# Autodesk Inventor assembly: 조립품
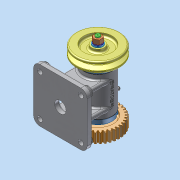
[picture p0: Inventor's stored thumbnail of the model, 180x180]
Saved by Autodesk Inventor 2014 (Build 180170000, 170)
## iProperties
Created: 2025-10
Part Number: 조립품
Document SubType Name: Assembly
Designer: dg
Author: dg
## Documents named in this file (17)
- C:\Users\dg\Desktop\751003V1009\조립품.iam
- C:\Users\dg\Desktop\751003V1009\본체.ipt
- C:\Users\dg\Desktop\751003V1009\가져온 구성요소\평 와셔 M8\평 와셔 M8.ipt
- C:\Users\dg\Desktop\751003V1009\가져온 구성요소\평행 키 3x3x12\평행 키 3x3x12.ipt
- C:\Users\dg\Desktop\751003V1009\가져온 구성요소\6각 구멍붙이 볼트 M4x10\6각 구멍붙이 볼트 M4x10.ipt
- C:\Users\dg\Desktop\751003V1009\가져온 구성요소\6각 너트 M8x1\6각 너트 M8x1.ipt
- C:\Users\dg\Desktop\751003V1009\가져온 구성요소\6각 머리 볼트 M6x0.75x8\6각 머리 볼트 M6x0.75x8.ipt
- C:\Users\dg\Desktop\751003V1009\가져온 구성요소\V 벨트 풀리\V 벨트 풀리.ipt
- C:\Users\dg\Desktop\751003V1009\가져온 구성요소\가스켓\가스켓.ipt
- C:\Users\dg\Desktop\751003V1009\가져온 구성요소\그리스 니플 M6x0.75\그리스 니플 M6x0.75.ipt
- C:\Users\dg\Desktop\751003V1009\가져온 구성요소\깊은 홈 볼 베어링 6002\깊은 홈 볼 베어링 6002.ipt
- C:\Users\dg\Desktop\751003V1009\가져온 구성요소\스퍼 기어\스퍼 기어.ipt
- C:\Users\dg\Desktop\751003V1009\가져온 구성요소\스프링 와셔 M8\스프링 와셔 M8.ipt
- C:\Users\dg\Desktop\751003V1009\가져온 구성요소\실링\실링.ipt
- C:\Users\dg\Desktop\751003V1009\가져온 구성요소\오일 실 15 25 4\오일 실 15 25 4.ipt
- C:\Users\dg\Desktop\751003V1009\가져온 구성요소\축\축.ipt
- C:\Users\dg\Desktop\751003V1009\가져온 구성요소\커버\커버.ipt
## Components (14 placed, 6 different names)
1. 6각 구멍붙이 볼트 M4x10:1
2. 6각 너트 M8x1:1
3. 6각 머리 볼트 M6x0.75x8:1
4. V 벨트 풀리:1
5. 가스켓:1
6. 그리스 니플 M6x0.75:1
7. 가스켓:2
8. 6각 너트 M8x1:2
9. 그리스 니플 M6x0.75:2
10. 6각 구멍붙이 볼트 M4x10:2
11. 6각 구멍붙이 볼트 M4x10:3
12. 6각 구멍붙이 볼트 M4x10:4
13. 6각 구멍붙이 볼트 M4x10:5
14. 6각 구멍붙이 볼트 M4x10:6
